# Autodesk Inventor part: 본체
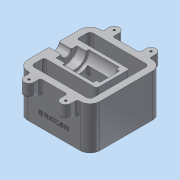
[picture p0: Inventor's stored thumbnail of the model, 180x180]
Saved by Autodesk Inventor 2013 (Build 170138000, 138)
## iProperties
Created: 2018-01
Part Number: 본체
Material: 알루미늄 6061
Document SubType Name: Modeling
Designer: dgall
Density: 2.71 g/cm^3
Mass: 999.005 g
Surface Area: 836.571 cm^2
Volume: 368.636 cm^3
Author: dgall
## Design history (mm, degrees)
sketch "스케치1"
  geometry: L1 (0, 0)-(110, 0); L2 (110, 0)-(110, 110); L3 (110, 110)-(0, 110); L4 (0, 110)-(0, 0); L5 (10, 100)-(100, 100); L6 (100, 100)-(100, 10); L7 (100, 10)-(10, 10); L8 (10, 10)-(10, 100)
  constraints: 16 end point, 4 parallel, 2 perpendicular, 1 horizontal, 3 other
  dimensions: "d0" = 110 distance of L1.start L1.end; "d1" = 110 distance of L1.end L2.end; "d2" = 10 distance between parallel lines of L5 L3
extrude "돌출1" new body sketch "스케치1" distance "d3" = 65; taper "d4" = 0 deg
sketch "스케치2"
  geometry: L1 (110, 110)-(0, 110) reference; L2 (0, 110)-(0, 0) reference; L3 (19.5, 120)-(19.5, 110); L4 (34.5, 120)-(34.5, 110); L5 (75.5, 120)-(75.5, 110); L6 (90.5, 120)-(90.5, 110); A1 r 7.5 centre (27, 120) between (34.5, 120) and (19.5, 120); A2 r 7.5 centre (83, 120) between (90.5, 120) and (75.5, 120)
  constraints: 8 end point, 4 perpendicular, 4 point on circle, 4 point on line, 4 tangent, 2 centre point, 1 horizontal alignment
  dimensions: "d5" = 15 diameter of A1; "d6" = 15 diameter of A2; "d7" = 27 distance from line of A1.centre L2; "d8" = 56 distance of A2.centre A1.centre; "d9" = 10 distance from line of A1.centre L1
extrude "돌출2" join sketch "스케치2" distance "d10" = 20; taper "d11" = 0 deg
node "작업 평면1"
sketch "스케치3"
  geometry: A1 r 7.5 centre (27, -10) between (19.5, -10) and (34.5, -10) reference; A2 r 7.5 centre (83, -10) between (75.5, -10) and (90.5, -10) reference; A3 r 7.5 centre (83, 120) between (90.5, 120) and (75.5, 120) reference; A4 r 7.5 centre (27, 120) between (34.5, 120) and (19.5, 120) reference; 4 further points
  constraints: 4 coincident
hole "구멍1" sketch "스케치3" at (27, 120), (83, 120), (27, -10), (83, -10) diameter "d12" = 3.242; stored, may be unused: countersink angle "d16" = 90 deg, drill point angle "d18" = 118 deg; dims "d13" = 9, "d14" = 4, "d15" = 2, "d17" = 11
node "작업 평면2"
sketch "스케치5"
  geometry: L1 (0, 0)-(0, 65) reference; L2 (0, 65)-(10, 65) reference; L3 (10, 65)-(10, 0) reference; L4 (10, 0)-(0, 0) reference; L5 (110, 65)-(110, 0) reference; L6 (110, 0)-(100, 0) reference; L7 (100, 0)-(100, 65) reference; L8 (100, 65)-(110, 65) reference; L9 (90, 65)-(90, 30); L10 (90, 30)-(10, 8.564); L11 (10, 65)-(10, 8.564); L12 (10, 65)-(90, 65); L13 (100, 0)-(10, 0) reference
  constraints: 8 end point, 2 perpendicular, 1 parallel, 1 point on line
  dimensions: "d22" = 20 distance between parallel lines of L5 L9; "d23" = 105 deg angle of L3 L10; "d24" = 30 distance from line of L13 L9.end
extrude "돌출3" join sketch "스케치5" distance "d25" = 50; taper "d26" = 0 deg
sketch "스케치6"
  geometry: L1 (65, 110)-(65, 0) reference; C1 r 7.5 at (65, 55)
  constraints: 1 centre point, 1 midpoint
  dimensions: "d27" = 15 diameter of C1
extrude "돌출4" cut sketch "스케치6" distance "d28" = 19; taper "d29" = 0 deg
sketch "스케치7"
  geometry: C1 r 16 at (65, 55); A1 r 7.5 centre (65, 55) between (65, 62.5) and (65, 47.5) reference; 1 further point
  constraints: 1 centre point, 1 coincident
  dimensions: "d30" = 32 diameter of C1
extrude "돌출5" cut sketch "스케치7" distance "d31" = 14; taper "d32" = 0 deg
sketch "스케치8"
  geometry: C1 r 20 at (65, 55); A1 r 16 centre (65, 55) between (65, 71) and (65, 39) reference; 1 further point
  constraints: 1 centre point, 1 coincident
  dimensions: "d33" = 40 diameter of C1
extrude "돌출6" cut sketch "스케치8" distance "d34" = 47; taper "d35" = 0 deg
sketch "스케치9"
  geometry: C1 r 15 at (65, 55); A1 r 20 centre (65, 55) between (65, 75) and (65, 35) reference; 1 further point
  constraints: 1 centre point, 1 coincident
  dimensions: "d36" = 30 diameter of C1
extrude "돌출7" cut sketch "스케치9" distance "d37" = 5; taper "d38" = 0 deg
fillet "모깎기1" dims "d39" = 3
fillet "모깎기2" dims "d40" = 3
node "작업 평면3"
sketch "스케치10"
  geometry: L1 (100, 65)-(110, 65) reference; L2 (110, 65)-(110, 0) reference; L3 (110, 0)-(100, 0) reference; L4 (100, 0)-(100, 65) reference; L5 (90, 30)-(10, 8.564) reference; L6 (10, 8.564)-(10, 0) reference; L7 (10, 0)-(0, 0) reference; L8 (0, 0)-(0, 57.5) reference; L9 (0, 57.5)-(19, 57.5) reference; L10 (19, 57.5)-(19, 49) reference; L11 (19, 49)-(33, 49) reference; L12 (33, 49)-(33, 45) reference; L13 (33, 45)-(80, 45) reference; L14 (80, 45)-(80, 50) reference; L15 (80, 50)-(85, 50) reference; L16 (85, 50)-(85, 65) reference; L17 (85, 65)-(90, 65) reference; L18 (90, 65)-(90, 30) reference; L19 (38, 50)-(38, 39.243); L20 (38, 39.243)-(0, 29.061); L21 (38, 50)-(75, 50); L22 (75, 50)-(75, 31.157); L23 (75, 31.157)-(0, 11.061); L24 (100, 65)-(110, 65) reference; L25 (110, 65)-(110, 0) reference; L26 (110, 0)-(100, 0) reference; L27 (100, 0)-(100, 65) reference; L28 (90, 30)-(10, 8.564) reference; L29 (10, 8.564)-(10, 0) reference; L30 (10, 0)-(0, 0) reference; L31 (0, 0)-(0, 57.5) reference; L32 (0, 57.5)-(19, 57.5) reference; L33 (19, 57.5)-(19, 49) reference; L34 (19, 49)-(33, 49) reference; L35 (33, 49)-(33, 45) reference; L36 (33, 45)-(80, 45) reference; L37 (80, 45)-(80, 50) reference; L38 (80, 50)-(85, 50) reference; L39 (85, 50)-(85, 65) reference; L40 (85, 65)-(90, 65) reference; L41 (90, 65)-(90, 30) reference; L42 (33, 65)-(80, 65) reference; 2 further points
  constraints: 10 end point, 3 parallel, 2 midpoint, 2 perpendicular, 2 point on line, 1 vertical alignment
  dimensions: "d41" = 5 distance between parallel lines of L5 L23; "d42" = 37 distance between parallel lines of L22 L19; "d43" = 18 distance of L23.end L20.end; "d44" = 5 distance between parallel lines of L13 L21
extrude "돌출8" cut sketch "스케치10" stored distance "d45" = 30; taper "d46" = 0 deg
chamfer "모따기1" distance "d47" = 1; stored, may be unused: second distance "d48" = 2, angle "d49" = 45 deg
fillet "모깎기3" dims "d50" = 1
fillet "모깎기4" dims "d51" = 15
fillet "모깎기5" dims "d52" = 5
fillet "모깎기6" dims "d53" = 3
fillet "모깎기7" dims "d54" = 3
fillet "모깎기8" dims "d55" = 3
fillet "모깎기9" dims "d56" = 3
fillet "모깎기10" dims "d57" = 3
fillet "모깎기11" dims "d58" = 3
fillet "모깎기12" dims "d59" = 3
fillet "모깎기13" dims "d60" = 3
fillet "모깎기14" dims "d61" = 3
fillet "모깎기15" dims "d62" = 3
fillet "모깎기16" dims "d63" = 1
fillet "모깎기17" dims "d68" = 3
sketch "스케치12" dims "d5" = 15, "d6" = 15, "d7" = 27, "d8" = 56, "d9" = 10
  geometry: L1 (-22.5, -65)-(57.5, -65) reference; L2 (-37.5, 0)-(-37.5, -65) reference; 1 further point
  constraints: 1 other
  dimensions: "d69" = 20 distance from line of L1 point (17.5, -45); "d70" = 55 distance from line of L2 point (17.5, -45)
feature "엠보싱2" sketch "스케치12" dims "d5" = 15, "d6" = 15, "d7" = 27, "d8" = 56, "d9" = 10, "d71" = 0.5, "d72" = 0
node "솔리드1"
mirror "대칭1"
node "절단 모서리 투영1"
node "절단 모서리 투영2"
node "절단 모서리 투영3"
